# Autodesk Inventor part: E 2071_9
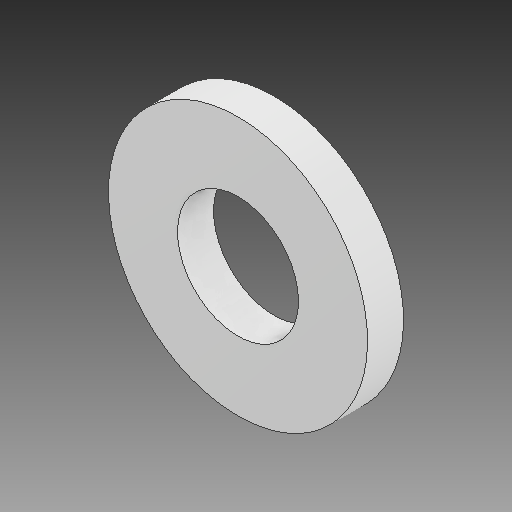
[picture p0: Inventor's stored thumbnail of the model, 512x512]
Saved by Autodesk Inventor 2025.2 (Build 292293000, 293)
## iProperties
Created: 2025-04
Part Number: E 2071_9
Material: Všeobecné
Document SubType Name: Modeling
Designer: Patrik
Density: 1 g/cm^3
Appearance: Výchozí
Mass: 0.497628 g
Surface Area: 6.05448 cm^2
Volume: 0.497628 cm^3
Author: Patrik
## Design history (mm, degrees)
feature "Base1"
node "Těleso1"
